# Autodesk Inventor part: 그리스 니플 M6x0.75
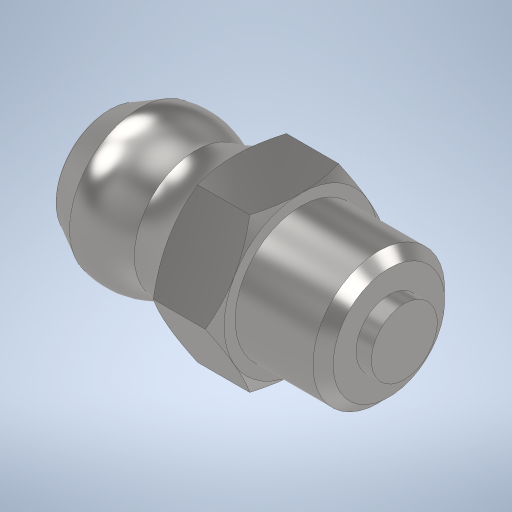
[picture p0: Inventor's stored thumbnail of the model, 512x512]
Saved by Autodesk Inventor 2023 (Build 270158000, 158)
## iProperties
Created: 2025-10
Part Number: 그리스 니플 M6x0.75
Material: 강철, 연강
Description: 윤활 니플, 원추 유형 A
Document SubType Name: Modeling
Designer: home
Density: 7.85 g/cm^3
Appearance: 기본값
Author: jhkim
Sending System: Autodesk Inventor 2026
Preprocessor: ST-DEVELOPER v20.1
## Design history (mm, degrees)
sketch "스케치1"
  geometry: 1 further point
  constraints: 1 other
feature "Solid1"
node "솔리드1"
